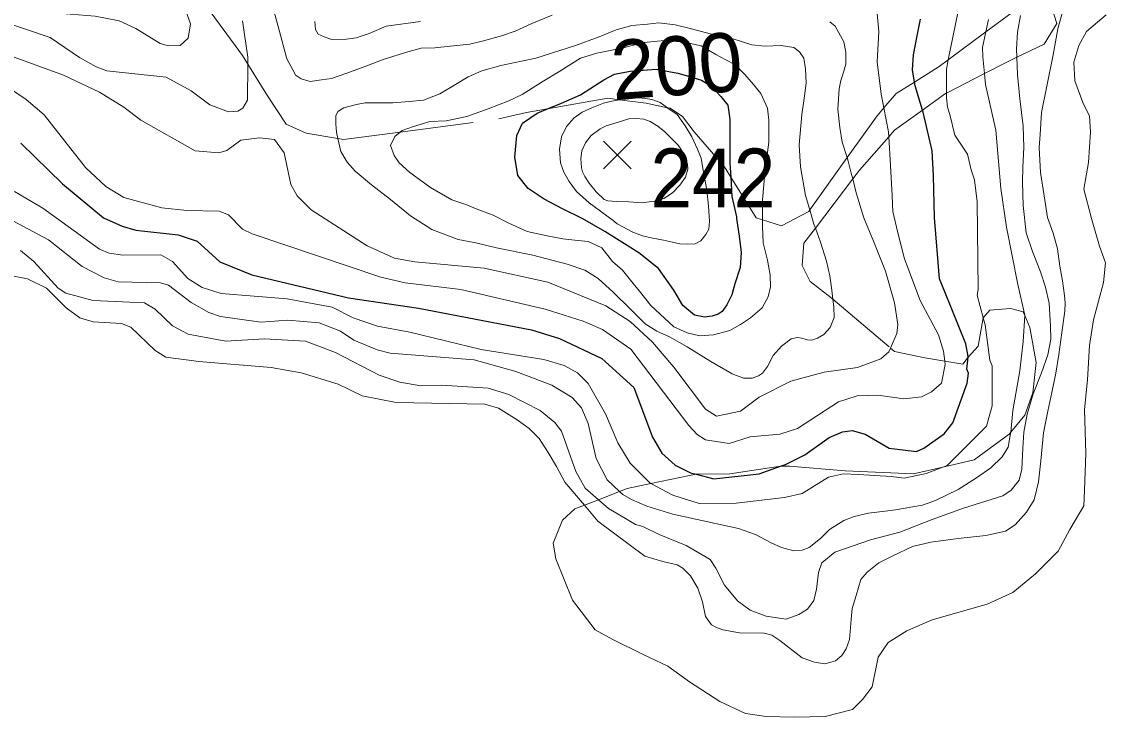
# Model space of a CAD drawing. Extents: x 474.5 to 500, y 7345.7 to 7373.4.
# Drawn here: x 486.724 to 488.197, y 7366.15 to 7367.094 of the extents above; entities that cross this region are included whole.
import ezdxf
from ezdxf.enums import TextEntityAlignment as Align

# ---------------------------------------------------------------- set-up
doc = ezdxf.new("R2010")
doc.units = 0
doc.header["$LTSCALE"] = 0.032
doc.linetypes.add('SHORT_DASHED', pattern=[2.7, 1.5, -1.2])
for name, color, linetype, lineweight in [('1', 7, 'Continuous', 25), ('16', 7, 'SHORT_DASHED', 13), ('2', 7, 'Continuous', 13), ('21', 7, 'Continuous', 25)]:
    doc.layers.add(name, color=color, linetype=linetype, lineweight=lineweight)
doc.layers.add('61', color=7, linetype='Continuous')

msp = doc.modelspace()

# ---------------------------------------------------------------- linework, layer by layer
at = {"layer": '1'}
for points in [[(487.9702, 7366.7454), (487.9635, 7366.8285), (487.9622, 7366.8851), (487.9601, 7366.9192), (487.9478, 7366.9717), (487.947, 7366.9742), (487.9369, 7367.0071), (487.9361, 7367.0122), (487.9335, 7367.0289), (487.9349, 7367.0494), (487.9397, 7367.0753), (487.9444, 7367.0977)], [(486.7225, 7366.9293), (486.7792, 7366.8741), (486.835, 7366.8281), (486.8602, 7366.8168), (486.8789, 7366.8115), (486.936, 7366.8051), (486.9622, 7366.7964), (486.9928, 7366.7685), (487.0363, 7366.7509), (487.1674, 7366.7197), (487.2624, 7366.7056), (487.416, 7366.6759), (487.4539, 7366.6642), (487.5118, 7366.637), (487.5551, 7366.5977), (487.5804, 7366.5306), (487.5932, 7366.5086), (487.6112, 7366.4926), (487.632, 7366.482), (487.6398, 7366.48), (487.6638, 7366.4738), (487.7253, 7366.4807), (487.7543, 7366.4909), (487.7612, 7366.4933), (487.7871, 7366.5062), (487.8201, 7366.5299), (487.8384, 7366.5378), (487.8516, 7366.5394), (487.8694, 7366.5346), (487.9016, 7366.5155), (487.9389, 7366.5108), (487.949, 7366.5154), (487.9766, 7366.535), (487.9882, 7366.5497), (488.0079, 7366.6036), (488.0097, 7366.6171), (488.0075, 7366.6225), (488.0089, 7366.639), (488.009, 7366.64), (488.0059, 7366.6572), (487.9773, 7366.7275), (487.9702, 7366.7454)]]:
    msp.add_lwpolyline(points, dxfattribs=at)
msp.add_lwpolyline([(487.5618, 7366.7806), (487.5158, 7366.8094), (487.4856, 7366.8266), (487.4581, 7366.8403), (487.4334, 7366.8534), (487.4114, 7366.8678), (487.3976, 7366.8857), (487.3935, 7366.9104), (487.3963, 7366.94), (487.4038, 7366.9565), (487.4237, 7366.9702), (487.4378, 7366.976), (487.4567, 7366.9839), (487.4828, 7366.9949), (487.5144, 7367.0155), (487.5289, 7367.0231), (487.5502, 7367.0272), (487.5852, 7367.03), (487.6147, 7367.0245), (487.6292, 7367.0204), (487.647, 7367.0149), (487.6594, 7367.0073), (487.6732, 7366.9929), (487.6828, 7366.9812), (487.6855, 7366.9619), (487.6855, 7366.9427), (487.6855, 7366.9262), (487.6855, 7366.9022), (487.6867, 7366.8833), (487.6883, 7366.8568), (487.6945, 7366.8293), (487.6945, 7366.8273), (487.6979, 7366.8032), (487.7006, 7366.7812), (487.6993, 7366.7606), (487.6924, 7366.7386), (487.6883, 7366.7235), (487.6814, 7366.7098), (487.6752, 7366.7009), (487.6697, 7366.6974), (487.6615, 7366.6947), (487.6512, 7366.6933), (487.6374, 7366.696), (487.6216, 7366.7091), (487.6093, 7366.7297), (487.5886, 7366.7593)], close=True, dxfattribs=at)
at = {"layer": '16'}
for points in [[(486.6974, 7367.3228), (486.7471, 7367.2839), (486.814, 7367.2493), (486.8689, 7367.2175), (486.881, 7367.2104), (486.9165, 7367.1826), (486.9306, 7367.1716), (486.976, 7367.1132), (487.0235, 7367.0484), (487.0309, 7367.0365), (487.0575, 7366.9935), (487.0831, 7366.9551), (487.1102, 7366.9431), (487.1531, 7366.9356), (487.1606, 7366.9343), (487.2379, 7366.9445), (487.3718, 7366.9623), (487.4094, 7366.9711), (487.4378, 7366.976), (487.5197, 7366.9903)], [(488.1229, 7367.1132), (488.1294, 7367.0916), (488.1121, 7367.0636), (488.0752, 7367.0459), (488.0624, 7367.0398), (488.0313, 7367.0238), (487.9796, 7366.9973), (487.9782, 7366.9966), (487.947, 7366.9742), (487.9091, 7366.9469), (487.9012, 7366.938), (487.8616, 7366.8929), (487.8524, 7366.8808), (487.8016, 7366.814), (487.786, 7366.7936), (487.7838, 7366.7633), (487.7946, 7366.7417), (487.8227, 7366.7201), (487.8255, 7366.7177), (487.9037, 7366.6513), (487.9091, 7366.6467), (487.9501, 7366.6381), (487.9774, 7366.6335), (488.002, 7366.6294), (488.0089, 7366.639), (488.0226, 7366.6538), (488.0296, 7366.6923), (488.0387, 7366.7029), (488.0668, 7366.705), (488.084, 7366.7007), (488.0861, 7366.6956), (488.0927, 7366.6791), (488.1013, 7366.6316), (488.097, 7366.5905), (488.0862, 7366.5603), (488.067, 7366.5373), (488.0646, 7366.5344), (488.0171, 7366.4998), (487.9747, 7366.4898), (487.935, 7366.4804), (487.8421, 7366.4847), (487.7665, 7366.4912), (487.7543, 7366.4909), (487.6853, 7366.4804), (487.6398, 7366.48), (487.6305, 7366.4782), (487.578, 7366.4674), (487.5462, 7366.4609), (487.5357, 7366.4568), (487.507, 7366.4455), (487.4879, 7366.438), (487.4749, 7366.4329), (487.4581, 7366.4178), (487.4454, 7366.3866), (487.449, 7366.3651)], [(487.449, 7366.3651), (487.4717, 7366.309), (487.5024, 7366.269), (487.5264, 7366.2556), (487.5678, 7366.2356), (487.6012, 7366.2196), (487.6306, 7366.1982), (487.672, 7366.1715), (487.7067, 7366.1555), (487.7347, 7366.1515), (487.7734, 7366.1502), (487.8148, 7366.1515), (487.8522, 7366.1608), (487.8656, 7366.1742), (487.8789, 7366.1915), (487.8869, 7366.2316), (487.9003, 7366.2516), (487.9257, 7366.2677), (487.9604, 7366.2823), (488.0351, 7366.3037), (488.0699, 7366.3197), (488.1006, 7366.3451), (488.1313, 7366.3758), (488.1473, 7366.4052), (488.166, 7366.4372), (488.1673, 7366.4586), (488.1687, 7366.508), (488.1673, 7366.5681), (488.1713, 7366.6081), (488.174, 7366.6549), (488.1793, 7366.6896), (488.1927, 7366.7403), (488.1954, 7366.767), (488.1874, 7366.7897), (488.1767, 7366.8271), (488.166, 7366.8671), (488.1727, 7366.9032), (488.1753, 7366.9446), (488.174, 7366.9659), (488.1647, 7366.9846), (488.154, 7367.014), (488.1526, 7367.0394), (488.1593, 7367.0621), (488.17, 7367.0808), (488.1967, 7367.1035)], [(487.5197, 7366.9903), (487.5351, 7366.9884), (487.5717, 7366.9839), (487.6008, 7366.9775), (487.6045, 7366.9767), (487.6213, 7366.9655), (487.6369, 7366.9448), (487.678, 7366.8972), (487.6867, 7366.8833), (487.7212, 7366.8281), (487.7297, 7366.8254), (487.7557, 7366.8173), (487.7925, 7366.8368), (487.794, 7366.8389), (487.8448, 7366.9098), (487.8853, 7366.9664), (487.8945, 7366.9772), (487.9112, 7366.9966), (487.9361, 7367.0122), (487.9696, 7367.0333), (487.9821, 7367.0426), (488.0331, 7367.0803), (488.0689, 7367.1068)]]:
    msp.add_lwpolyline(points, dxfattribs=at)
at = {"layer": '2'}
for points in [[(486.7162, 7367.1193), (486.7557, 7367.1071), (486.8234, 7367.1019), (486.8561, 7367.0956), (486.8789, 7367.085), (486.9116, 7367.0647), (486.9231, 7367.0613), (486.939, 7367.0621), (486.9497, 7367.0717), (486.9528, 7367.0915), (486.9431, 7367.1189), (486.9288, 7367.1413), (486.9193, 7367.1636), (486.9165, 7367.1826), (486.9162, 7367.185), (486.9162, 7367.2086), (486.9146, 7367.2451), (486.914, 7367.2632)], [(487.4442, 7367.1032), (487.4163, 7367.0916), (487.3938, 7367.0814), (487.3754, 7367.0753), (487.3508, 7367.0684), (487.3324, 7367.0637), (487.3058, 7367.0609), (487.2847, 7367.0589), (487.2663, 7367.0582), (487.2479, 7367.0534), (487.2159, 7367.0432), (487.1852, 7367.0316), (487.1641, 7367.0241), (487.1443, 7367.0173), (487.1307, 7367.0153), (487.1157, 7367.0132), (487.1034, 7367.0166), (487.0953, 7367.0221), (487.0946, 7367.0241), (487.0837, 7367.0439), (487.072, 7367.0877), (487.0653, 7367.1127)], [(488.1388, 7367.1142), (488.131, 7367.0847), (488.1247, 7367.0493), (488.1159, 7367.0066), (488.1087, 7366.971), (488.107, 7366.9411), (488.1057, 7366.9236), (488.1074, 7366.8895), (488.1121, 7366.8577), (488.1167, 7366.8285), (488.1246, 7366.8073), (488.1306, 7366.7861), (488.1337, 7366.7623), (488.1374, 7366.7427), (488.14, 7366.7228), (488.141, 7366.7125), (488.1404, 7366.7016), (488.1364, 7366.6726), (488.1324, 7366.6425), (488.1281, 7366.6173), (488.1228, 7366.5909), (488.1172, 7366.5657), (488.1116, 7366.5362), (488.1079, 7366.4984), (488.1046, 7366.4696), (488.0988, 7366.4455), (488.0885, 7366.4286), (488.0729, 7366.4113), (488.0597, 7366.403), (488.0329, 7366.3971), (487.9954, 7366.3928), (487.9583, 7366.3878), (487.9336, 7366.3818), (487.9068, 7366.3692), (487.8876, 7366.36), (487.872, 7366.347), (487.8634, 7366.3374), (487.8568, 7366.3156), (487.8517, 7366.298), (487.8503, 7366.2828), (487.848, 7366.256), (487.8434, 7366.243), (487.8373, 7366.2341), (487.8287, 7366.2268), (487.8224, 7366.2248), (487.8144, 7366.2228), (487.8002, 7366.2251), (487.7836, 7366.2311), (487.7531, 7366.2543), (487.7425, 7366.2616), (487.7321, 7366.2646), (487.6986, 7366.2649), (487.6761, 7366.2689), (487.6675, 7366.2719), (487.6605, 7366.2755), (487.6522, 7366.2868), (487.6483, 7366.3067), (487.6418, 7366.3254), (487.632, 7366.342), (487.6214, 7366.3526), (487.6138, 7366.3569), (487.5946, 7366.3618), (487.5698, 7366.3691), (487.5063, 7366.4164), (487.4879, 7366.438), (487.4612, 7366.4694), (487.45, 7366.4906)], [(486.7047, 7367.0053), (486.73, 7366.9888), (486.7542, 7366.9678), (486.8102, 7366.8966), (486.8381, 7366.8706), (486.8625, 7366.8555), (486.914, 7366.8418), (486.9479, 7366.838), (486.9919, 7366.837), (487.0047, 7366.8322), (487.0234, 7366.8128), (487.0367, 7366.8064), (487.2113, 7366.7475), (487.2443, 7366.7397), (487.3203, 7366.731), (487.4348, 7366.704), (487.4863, 7366.6879), (487.5123, 7366.6766), (487.5508, 7366.6498), (487.6297, 7366.5463), (487.6411, 7366.5342), (487.6522, 7366.5266), (487.6843, 7366.522), (487.7132, 7366.5307), (487.7532, 7366.5344), (487.7775, 7366.5421), (487.833, 7366.5782), (487.8584, 7366.5865), (487.8866, 7366.5872), (487.9218, 7366.5826), (487.9456, 7366.585), (487.9594, 7366.592), (487.9728, 7366.6039), (487.978, 7366.6289), (487.9774, 7366.6335), (487.9758, 7366.6472), (487.9689, 7366.6695), (487.9441, 7366.7158), (487.9226, 7366.7724), (487.9136, 7366.8076), (487.9068, 7366.8368), (487.9059, 7366.8578), (487.9038, 7366.8989), (487.9012, 7366.938), (487.9008, 7366.9448), (487.8945, 7366.9772), (487.8909, 7366.9959), (487.8853, 7367.04), (487.8879, 7367.0808), (487.8849, 7367.1104)], [(486.7118, 7366.824), (486.7603, 7366.7981), (486.8059, 7366.7618), (486.8358, 7366.7468), (486.8545, 7366.7414), (486.9121, 7366.7397), (486.9231, 7366.7365), (486.954, 7366.7131), (486.978, 7366.6996), (486.9935, 7366.6942), (487.0484, 7366.6863), (487.085, 7366.6894), (487.1278, 7366.6854), (487.1565, 7366.6742), (487.1749, 7366.6622), (487.2063, 7366.6489), (487.2242, 7366.6446), (487.3384, 7366.6352), (487.3947, 7366.6196), (487.4437, 7366.6008), (487.4711, 7366.5843), (487.484, 7366.57), (487.493, 7366.5488), (487.5039, 7366.5015), (487.5188, 7366.4727), (487.5357, 7366.4568), (487.5402, 7366.4526), (487.552, 7366.4458), (487.5727, 7366.4366), (487.6081, 7366.4259), (487.6557, 7366.4156), (487.6974, 7366.4066), (487.7203, 7366.3981), (487.7414, 7366.3869), (487.7558, 7366.3806), (487.7724, 7366.3761), (487.7836, 7366.377), (487.793, 7366.3806), (487.8087, 7366.3927), (487.8209, 7366.4049), (487.8402, 7366.4174), (487.8541, 7366.4228), (487.8738, 7366.4273), (487.8963, 7366.43), (487.9102, 7366.4318), (487.947, 7366.4381), (487.9649, 7366.4443), (487.9954, 7366.4592), (488.0206, 7366.4753), (488.0399, 7366.4888), (488.0551, 7366.5036), (488.0632, 7366.517), (488.0668, 7366.5354), (488.067, 7366.5373), (488.0699, 7366.5664), (488.0794, 7366.6203), (488.0838, 7366.6602), (488.0861, 7366.6956), (488.0861, 7366.6961), (488.0767, 7366.7378), (488.061, 7366.8155), (488.0533, 7366.868), (488.0466, 7366.947), (488.0327, 7367.0089), (488.0313, 7367.0238), (488.0291, 7367.0466), (488.0286, 7367.0592), (488.0331, 7367.0803), (488.0367, 7367.0973)], [(486.7223, 7366.7836), (486.7402, 7366.7688), (486.7731, 7366.7328), (486.7835, 7366.7259), (486.8207, 7366.7158), (486.8906, 7366.7126), (486.9051, 7366.7043), (486.9287, 7366.6816), (486.9498, 7366.67), (487.0011, 7366.6609), (487.053, 7366.664), (487.109, 7366.6609), (487.1501, 7366.6454), (487.2093, 7366.6144), (487.2374, 7366.605), (487.2658, 7366.6002), (487.2945, 7366.6009), (487.3571, 7366.597), (487.3855, 7366.5884), (487.4277, 7366.5665), (487.4478, 7366.5503), (487.4567, 7366.5384), (487.4761, 7366.4836), (487.4891, 7366.4612), (487.507, 7366.4455), (487.5206, 7366.4335), (487.5415, 7366.4213), (487.5572, 7366.4119), (487.5674, 7366.4091), (487.5894, 7366.3985), (487.626, 7366.3835), (487.6586, 7366.3642), (487.6666, 7366.3527), (487.678, 7366.3293), (487.6957, 7366.3082), (487.7129, 7366.2954), (487.7349, 7366.2874), (487.7618, 7366.2835), (487.779, 7366.2897), (487.7909, 7366.2971), (487.7993, 7366.3086), (487.8032, 7366.324), (487.8059, 7366.3465), (487.8103, 7366.3597), (487.8279, 7366.3743), (487.8764, 7366.391), (487.9161, 7366.4016), (487.9602, 7366.4188), (488.0029, 7366.4342), (488.0563, 7366.4506), (488.0677, 7366.4585), (488.0783, 7366.4722), (488.0818, 7366.4871), (488.0832, 7366.5154), (488.0845, 7366.5374), (488.0893, 7366.5616), (488.0973, 7366.5894), (488.1087, 7366.6176), (488.1171, 7366.6423), (488.1215, 7366.6635), (488.1211, 7366.6811), (488.1193, 7366.7124), (488.114, 7366.734), (488.1074, 7366.7547), (488.0964, 7366.7825), (488.088, 7366.8076), (488.084, 7366.8447), (488.0827, 7366.8768), (488.0832, 7366.8962), (488.0845, 7366.924), (488.0836, 7366.9527), (488.0792, 7366.9897), (488.0761, 7367.0228), (488.0752, 7367.0459), (488.0748, 7367.0576), (488.0761, 7367.0801), (488.0801, 7367.1025)], [(486.9127, 7366.778), (486.9285, 7366.7689), (486.9493, 7366.7457), (486.9687, 7366.7337), (486.9944, 7366.7252), (487.0842, 7366.7182), (487.1454, 7366.7069), (487.1741, 7366.6925), (487.2067, 7366.6811), (487.2507, 7366.6727), (487.3476, 7366.6492), (487.4326, 7366.636), (487.4605, 7366.6275), (487.4785, 7366.6176), (487.4929, 7366.6033), (487.5167, 7366.5621), (487.5333, 7366.5226), (487.5499, 7366.4951), (487.5776, 7366.4676), (487.578, 7366.4674), (487.6081, 7366.4516), (487.6436, 7366.4404), (487.6942, 7366.4407), (487.7595, 7366.4487), (487.7836, 7366.454), (487.8196, 7366.4762), (487.8399, 7366.4804), (487.8602, 7366.4796), (487.9043, 7366.4771), (487.9224, 7366.4749), (487.9521, 7366.4812), (487.9747, 7366.4898), (487.9808, 7366.4921), (488.0338, 7366.5452), (488.0417, 7366.5728), (488.0417, 7366.6272), (488.0386, 7366.6349), (488.0322, 7366.683), (488.0296, 7366.6923), (488.0211, 7366.7229), (488.0226, 7366.7309), (488.0211, 7366.8497), (488.0178, 7366.8798), (488.0131, 7366.8934), (488.0082, 7366.9143), (487.9912, 7366.9401), (487.9844, 7366.9684), (487.9809, 7366.9782), (487.9796, 7366.991), (487.9796, 7366.9973), (487.9796, 7367.0299), (487.9821, 7367.0426), (487.9953, 7367.1087)], [(486.6956, 7367.0954), (486.7624, 7367.073), (486.8021, 7367.0457), (486.8249, 7367.033), (486.8394, 7367.0277), (486.9199, 7367.0189), (486.9539, 7367.0004), (486.9794, 7366.9813), (487.0045, 7366.9719), (487.0174, 7366.9728), (487.0241, 7366.9769), (487.0303, 7366.9876), (487.0309, 7367.0365), (487.031, 7367.0459), (487.0238, 7367.0953)], [(487.2652, 7367.0945), (487.2189, 7367.0881), (487.1957, 7367.0782), (487.1781, 7367.0722), (487.1649, 7367.0705), (487.1447, 7367.07), (487.1344, 7367.0735), (487.1263, 7367.0773), (487.1228, 7367.0838), (487.122, 7367.0945)], [(487.8402, 7367.0269), (487.8429, 7367.0364), (487.8429, 7367.0528), (487.8402, 7367.0671), (487.8286, 7367.0882), (487.8211, 7367.0943)], [(486.6746, 7367.0603), (486.7804, 7367.0217), (486.8294, 7366.9988), (486.8625, 7366.9784), (486.8856, 7366.9604), (486.9592, 7366.9188), (486.9913, 7366.9165), (487.0024, 7366.9195), (487.0211, 7366.9336), (487.0467, 7366.9368), (487.0671, 7366.9346), (487.0803, 7366.9163), (487.0893, 7366.8735), (487.0979, 7366.8578), (487.1168, 7366.8391), (487.1928, 7366.7899), (487.2302, 7366.7734), (487.2577, 7366.7683), (487.352, 7366.7597), (487.4384, 7366.7406), (487.5171, 7366.7085), (487.5501, 7366.6872), (487.5803, 7366.6595), (487.6095, 7366.6254), (487.6522, 7366.5685), (487.6672, 7366.5587), (487.6999, 7366.5657), (487.7252, 7366.5845), (487.7683, 7366.6063), (487.8134, 7366.6184), (487.8586, 7366.6249), (487.8907, 7366.6367), (487.9014, 7366.646), (487.9037, 7366.6513), (487.9123, 7366.6713), (487.9134, 7366.6831), (487.909, 7366.7127), (487.8967, 7366.7556), (487.8804, 7366.7965), (487.8674, 7366.8279), (487.8572, 7366.8619), (487.8524, 7366.8808), (487.8504, 7366.8885), (487.8463, 7366.9049), (487.8448, 7366.9098), (487.8381, 7366.9308), (487.8347, 7366.9505), (487.832, 7366.9757), (487.834, 7367.003), (487.8361, 7367.0146), (487.8402, 7367.0269)], [(486.7138, 7366.8636), (486.7524, 7366.8412), (486.8294, 7366.7854), (486.8423, 7366.7803), (486.8609, 7366.7773), (486.9127, 7366.778)], [(487.45, 7366.4906), (487.4385, 7366.5097), (487.4263, 7366.5288), (487.4129, 7366.5422), (487.3964, 7366.5541), (487.3714, 7366.5699), (487.3528, 7366.5753), (487.2321, 7366.5776), (487.1863, 7366.5866), (487.1535, 7366.6022), (487.1034, 7366.6177), (487.0626, 7366.6248), (486.9641, 7366.6329), (486.9193, 7366.639), (486.9051, 7366.6478), (486.872, 7366.6799), (486.8592, 7366.6847), (486.8207, 7366.6871), (486.8025, 7366.6924), (486.7841, 7366.7059), (486.7573, 7366.7325), (486.7318, 7366.7453), (486.6621, 7366.7587)]]:
    msp.add_lwpolyline(points, dxfattribs=at)
for points in [[(487.4178, 7366.7773), (487.3684, 7366.7875), (487.3403, 7366.7943), (487.3164, 7366.7986), (487.2807, 7366.8122), (487.2517, 7366.831), (487.2244, 7366.8531), (487.1989, 7366.8727), (487.1767, 7366.8915), (487.1656, 7366.9034), (487.1571, 7366.9179), (487.1531, 7366.9356), (487.1512, 7366.9443), (487.1503, 7366.9554), (487.1503, 7366.9596), (487.1503, 7366.9664), (487.1529, 7366.9724), (487.1614, 7366.9775), (487.1784, 7366.9818), (487.1903, 7366.9843), (487.204, 7366.9843), (487.2278, 7366.9843), (487.25, 7366.986), (487.2696, 7366.9877), (487.2917, 7366.9963), (487.313, 7367.009), (487.3301, 7367.0193), (487.3488, 7367.0278), (487.3744, 7367.0346), (487.4221, 7367.0448), (487.4758, 7367.0619), (487.5081, 7367.0738), (487.5311, 7367.0832), (487.5524, 7367.0891), (487.5737, 7367.0908), (487.5891, 7367.0925), (487.6112, 7367.09), (487.6317, 7367.0849), (487.6606, 7367.0772), (487.6913, 7367.0704), (487.7152, 7367.0627), (487.7331, 7367.061), (487.7552, 7367.0619), (487.7723, 7367.0593), (487.7799, 7367.0533), (487.7859, 7367.0448), (487.7884, 7367.0303), (487.7893, 7367.0107), (487.7859, 7366.9869), (487.7833, 7366.9681), (487.7797, 7366.9273), (487.7816, 7366.8974), (487.7884, 7366.8582), (487.794, 7366.8389), (487.7996, 7366.8194), (487.8016, 7366.814), (487.8085, 7366.795), (487.8168, 7366.7692), (487.8212, 7366.7493), (487.824, 7366.7297), (487.8255, 7366.7177), (487.8268, 7366.7074), (487.8271, 7366.693), (487.8217, 7366.6793), (487.8132, 7366.6699), (487.8046, 7366.6648), (487.7968, 7366.662), (487.791, 7366.6623), (487.7834, 7366.6648), (487.7774, 7366.6657), (487.7689, 7366.664), (487.7556, 7366.6541), (487.7441, 7366.641), (487.7365, 7366.6265), (487.7297, 7366.6171), (487.7245, 7366.6137), (487.716, 7366.6103), (487.7041, 7366.6103), (487.6888, 7366.6163), (487.6598, 7366.6333), (487.6274, 7366.6529), (487.6036, 7366.6665), (487.5865, 7366.6742), (487.5703, 7366.6844), (487.5507, 7366.704), (487.5269, 7366.727), (487.5064, 7366.7458), (487.4885, 7366.7569), (487.4647, 7366.7654)], [(487.4102, 7366.8097), (487.3855, 7366.8208), (487.3642, 7366.8318), (487.3411, 7366.8403), (487.3284, 7366.8455), (487.3079, 7366.8523), (487.279, 7366.8693), (487.2508, 7366.8898), (487.2364, 7366.9025), (487.2295, 7366.9128), (487.2244, 7366.9264), (487.2304, 7366.9383), (487.2379, 7366.9445), (487.2406, 7366.9468), (487.256, 7366.952), (487.2696, 7366.9562), (487.2781, 7366.9588), (487.3003, 7366.9596), (487.3284, 7366.9656), (487.3573, 7366.9758), (487.3855, 7366.9869), (487.4033, 7366.9954), (487.4306, 7367.0125), (487.4545, 7367.0269), (487.4826, 7367.0448), (487.5047, 7367.0516), (487.5388, 7367.0585), (487.5686, 7367.0661), (487.5967, 7367.0687), (487.6237, 7367.0667), (487.6467, 7367.0616), (487.6666, 7367.0499), (487.68, 7367.0423), (487.6922, 7367.0363), (487.7058, 7367.0227), (487.7177, 7367.009), (487.7274, 7366.9966), (487.7364, 7366.9767), (487.7382, 7366.9605), (487.7382, 7366.9307), (487.7365, 7366.917), (487.7331, 7366.8881), (487.7297, 7366.8523), (487.7297, 7366.8254), (487.7297, 7366.8165), (487.7305, 7366.7943), (487.7365, 7366.7705), (487.7401, 7366.7503), (487.7405, 7366.7345), (487.7374, 7366.7208), (487.7292, 7366.7057), (487.7137, 7366.6923), (487.6999, 7366.6833), (487.6854, 7366.6751), (487.6632, 7366.6691), (487.6446, 7366.6679), (487.6275, 7366.672), (487.6095, 7366.6802), (487.578, 7366.7091), (487.5628, 7366.7286), (487.5541, 7366.739), (487.5397, 7366.7569), (487.526, 7366.7688), (487.5115, 7366.7875), (487.4928, 7366.796), (487.4749, 7366.7977), (487.4587, 7366.7995), (487.4374, 7366.8037)], [(487.5268, 7366.8245), (487.4945, 7366.8486), (487.4773, 7366.8637), (487.467, 7366.8774), (487.4602, 7366.8901), (487.4553, 7366.9029), (487.454, 7366.9211), (487.4567, 7366.9379), (487.4636, 7366.952), (487.4739, 7366.964), (487.4849, 7366.9716), (487.4979, 7366.9774), (487.5137, 7366.9836), (487.523, 7366.986), (487.535, 7366.9884), (487.5351, 7366.9884), (487.5402, 7366.9887), (487.5567, 7366.9905), (487.5612, 7366.9908), (487.5711, 7366.9898), (487.5794, 7366.9887), (487.5907, 7366.9846), (487.6008, 7366.9775), (487.6014, 7366.9771), (487.6137, 7366.9685), (487.6247, 7366.953), (487.6336, 7366.9379), (487.6415, 7366.9214), (487.6464, 7366.909), (487.6484, 7366.8977), (487.6543, 7366.8658), (487.6563, 7366.8441), (487.6577, 7366.8235), (487.6567, 7366.8125), (487.6529, 7366.8053), (487.646, 7366.7967), (487.6385, 7366.7926), (487.6275, 7366.7922), (487.6175, 7366.7929), (487.6075, 7366.795), (487.5952, 7366.7977), (487.5787, 7366.8008), (487.567, 7366.8036), (487.5539, 7366.8084), (487.5326, 7366.8197)], [(487.5484, 7366.8496), (487.5316, 7366.8503), (487.5196, 7366.851), (487.5148, 7366.853), (487.5038, 7366.8634), (487.4942, 7366.875), (487.4887, 7366.884), (487.4852, 7366.8905), (487.4839, 7366.896), (487.4832, 7366.9087), (487.4845, 7366.919), (487.4894, 7366.93), (487.4969, 7366.9396), (487.5093, 7366.9489), (487.5175, 7366.953), (487.5309, 7366.9568), (487.5484, 7366.9626), (487.5584, 7366.963), (487.5684, 7366.9619), (487.577, 7366.9589), (487.5876, 7366.9527), (487.5972, 7366.9448), (487.6058, 7366.9362), (487.6151, 7366.9266), (487.6237, 7366.9135), (487.6281, 7366.9011), (487.6285, 7366.8939), (487.6254, 7366.8833), (487.6175, 7366.8726), (487.6075, 7366.862), (487.5959, 7366.8541), (487.5869, 7366.8513), (487.5759, 7366.85), (487.5667, 7366.8486)]]:
    msp.add_lwpolyline(points, close=True, dxfattribs=at)
at = {"layer": '21'}
for p, q in [((487.5139, 7366.9319), (487.5514, 7366.8944)), ((487.5514, 7366.9319), (487.5139, 7366.8944))]:
    msp.add_line(p, q, dxfattribs=at)

# ---------------------------------------------------------------- texts
at = {"layer": '61'}
msp.add_text('200', height=0.08, rotation=4.01, dxfattribs=at).set_placement((487.616, 7366.9946), align=Align.CENTER)
at = {"layer": '61', "width": 0.95}
msp.add_text('242', height=0.08, dxfattribs=at).set_placement((487.6624, 7366.8421), align=Align.CENTER)

doc.saveas('drawing.dxf')
